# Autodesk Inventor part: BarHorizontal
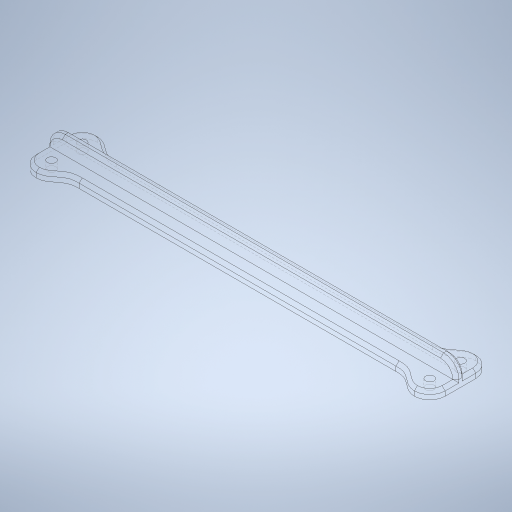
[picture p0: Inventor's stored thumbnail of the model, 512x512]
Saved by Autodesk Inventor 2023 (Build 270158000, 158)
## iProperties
Created: 2023-10
Part Number: BarHorizontal
Material: Aluminum 7075
Document SubType Name: Modeling
Designer: tornqvih
Density: 2.81 g/cm^3
Appearance: Satin - Brushed Heavy
Mass: 170.421 g
Surface Area: 211.773 cm^2
Volume: 60.6482 cm^3
Author: tornqvih
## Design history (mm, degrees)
sketch "Sketch1"
  geometry: L1 (103, -12)-(-103, -12); L2 (-103, 12)-(103, 12); L3 (0, -30.899)-(0, 30.899) reference; L4 (133, -10)-(133, 10); L5 (189.099, 0)-(-189.099, 0) reference; L6 (-133, -10)-(-133, 10); A1 r 10 centre (123, -10) between (123, -20) and (133, -10); A2 r 10 centre (123, 10) between (133, 10) and (123, 20); A3 r 10 centre (-123, -10) between (-133, -10) and (-123, -20); A4 r 10 centre (-123, 10) between (-123, 20) and (-133, 10)
  constraints: 11 symmetric about line, 8 end point, 8 point on circle, 4 centre point, 4 horizontal, 2 vertical alignment, 1 horizontal alignment, 1 vertical, 12 other
  dimensions: "d38" = 10 radius of A1; "d40" = 12 distance between parallel lines of L5 L1; "d41" = 123 distance from line of L3 A1.centre; "d43" = 103 distance from line of L3 L1.start; "d49" = 10 distance from line of L5 A1.centre
extrude "Extrusion2" new body sketch "Sketch1" distance "d13" = 5; taper "d14" = 0 deg
sketch "Sketch3"
  geometry: L1 (-186.2, 0)-(186.2, 0) reference; L2 (0, 28)-(0, -28) reference; 6 further points
  constraints: 3 symmetric about line
  dimensions: "d34" = 10 distance from line of L1 point (-123, 10); "d42" = 123 distance from line of L2 point (-123, 10)
hole "Hole1" sketch "Sketch3" at (-123, 10), (-123, -10), (123, 10), (123, -10) diameter "d15" = 5.5; stored, may be unused: countersink angle "d19" = 90 deg, drill point angle "d21" = 118 deg; dims "d16" = 6, "d17" = 4, "d18" = 2, "d20" = 8
sketch "Sketch4"
  geometry: L1 (-123, 5)-(-133, 5) reference; L2 (123, 0)-(123, 5) reference; L3 (133, 5)-(123, 5) reference; L4 (-123, 15)-(123, 15); L5 (-133, 5)-(133, 5); A1 r 10 centre (-123, 5) between (-123, 15) and (-133, 5); A2 r 10 centre (123, 5) between (133, 5) and (123, 15); 3 further points
  constraints: 4 end point, 4 point on circle, 2 centre point, 1 collinear, 1 horizontal
extrude "Extrusion3" join sketch "Sketch4" stored distance "d44" = 6; taper "d45" = 0 deg
chamfer "Chamfer1" distance "d46" = 2; stored, may be unused: second distance "d47" = 2, angle "d48" = 45 deg
body "Solid2"
